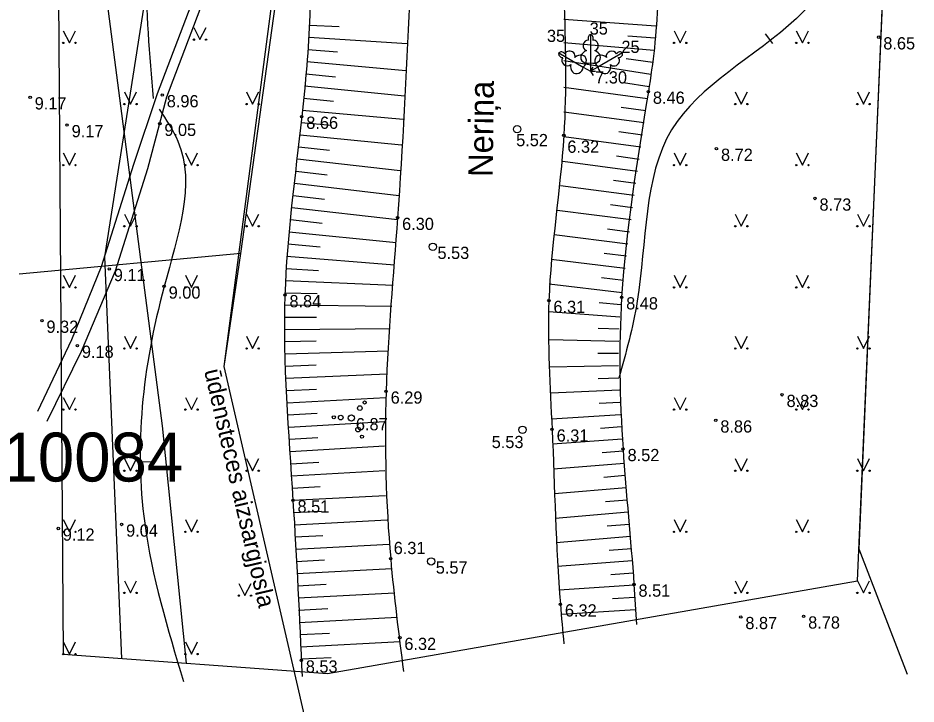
# Model space of a CAD drawing. Extents: x 496127 to 496334, y 303823 to 303967.
# Drawn here: x 496197.9 to 496234.65, y 303857.96 to 303886.02 of the extents above; entities that cross this region are included whole.
import ezdxf

# ---------------------------------------------------------------- set-up
doc = ezdxf.new("R2010")
doc.units = 0
for name, color, linetype in [('APGR_AIZS_####_####_#', 7, 'Continuous'), ('APGR_AIZS_####_TKST_#', 7, 'Continuous'), ('CELI_TAKA_####_####_#', 7, 'Continuous'), ('GAZE_VADP_ASP1_####_#', 7, 'Continuous'), ('HIDG_AATZ_####_TKST_#', 7, 'Continuous'), ('HIDG_ELEM_####_####_#', 7, 'Continuous'), ('HIDG_HNOS_####_TKST_#', 7, 'Continuous'), ('HIDG_PLIN_####_####_#', 7, 'Continuous'), ('Level 24', 7, 'Continuous'), ('Level 59', 7, 'Continuous'), ('RAMI_UZMR_####_####_#', 7, 'Continuous'), ('RELJ_AATZ_####_TKST_#', 7, 'Continuous'), ('RELJ_ELEM_####_####_#', 7, 'Continuous'), ('RELJ_HORZ_PAMT_####_#', 7, 'Continuous'), ('RELJ_NOGA_####_####_#', 7, 'Continuous'), ('SAKT_VADP_KABE_####_#', 7, 'Continuous'), ('TERT_DIAM_####_TKST_#', 7, 'Continuous'), ('TERT_ELEM_####_####_#', 7, 'Continuous')]:
    doc.layers.add(name, color=color, linetype=linetype)

msp = doc.modelspace()

# ---------------------------------------------------------------- linework, layer by layer
at = {"layer": 'APGR_AIZS_####_####_#'}
msp.add_lwpolyline([(496206.5, 303871.056), (496206.335, 303871.77), (496213.935, 303929.615)], dxfattribs=at)
at = {"layer": 'CELI_TAKA_####_####_#'}
for points in [[(496198.714, 303869.933), (496200.104, 303872.87), (496201.314, 303875.855), (496202.637, 303880.037), (496203.613, 303882.939), (496206.254, 303889.883), (496210.709, 303896.123), (496215.063, 303897.39)], [(496199.09, 303869.522), (496200.5, 303872.394), (496201.881, 303875.679), (496203.215, 303879.862), (496203.987, 303882.797), (496206.61, 303889.693), (496210.953, 303895.777), (496213.057, 303896.39)]]:
    msp.add_lwpolyline(points, dxfattribs=at)
at = {"layer": 'GAZE_VADP_ASP1_####_#'}
msp.add_lwpolyline([(496204.788, 303859.627), (496203.806, 303869.341), (496199.437, 303902.962)], dxfattribs=at)
at = {"layer": 'HIDG_ELEM_####_####_#'}
for centre in [(496218.324, 303881.471), (496214.879, 303876.663), (496218.547, 303869.176), (496214.81, 303863.79)]:
    msp.add_circle(centre, 0.15, dxfattribs=at)
at = {"layer": 'HIDG_PLIN_####_####_#'}
for points in [[(496220.243, 303886.863), (496220.236, 303881.217), (496219.625, 303874.455), (496219.756, 303869.191), (496220.095, 303862.036), (496220.238, 303860.42)], [(496213.924, 303886.643), (496213.431, 303877.849), (496212.963, 303870.744), (496213.15, 303863.904), (496213.673, 303859.283)]]:
    msp.add_spline(points, degree=3, dxfattribs=at)
at = {"layer": 'Level 24'}
for points in [[(496207.017, 303876.387), (496214.972, 303933.586)], [(496234.652, 303919.252), (496232.313, 303864.302)], [(496207.017, 303876.387), (496197.941, 303875.547)], [(496206.335, 303871.77), (496207.017, 303876.387)], [(496210.502, 303853.691), (496206.335, 303871.77)], [(496232.313, 303864.302), (496234.289, 303859.174)]]:
    msp.add_lwpolyline(points, dxfattribs=at)
at = {"layer": 'RAMI_UZMR_####_####_#'}
for p, q in [((496232.25, 303863), (496234.504, 303914.713)), ((496199.386, 303909.951), (496199.75, 303860)), ((496210.565, 303859.199), (496232.25, 303863)), ((496199.75, 303860), (496210.565, 303859.199))]:
    msp.add_line(p, q, dxfattribs=at)
at = {"layer": 'RELJ_ELEM_####_####_#'}
for centre in [(496233.126, 303885.236), (496223.696, 303883.01), (496198.395, 303882.78), (496203.8, 303882.868), (496209.51, 303881.987), (496199.907, 303881.643), (496203.702, 303881.695), (496220.236, 303881.217), (496226.484, 303880.676), (496230.515, 303878.639), (496213.431, 303877.849), (496201.634, 303875.756), (496203.878, 303875.039), (496208.821, 303874.686), (496222.602, 303874.598), (496219.625, 303874.455), (496198.876, 303873.641), (496200.326, 303872.617), (496212.963, 303870.744), (496229.167, 303870.606), (496226.456, 303869.561), (496219.756, 303869.191), (496222.659, 303868.391), (496209.151, 303866.287), (496199.545, 303865.137), (496202.136, 303865.302), (496213.15, 303863.904), (496223.107, 303862.846), (496220.095, 303862.036), (496227.48, 303861.519), (496230.051, 303861.541), (496213.524, 303860.667), (496209.49, 303859.74)]:
    msp.add_circle(centre, 0.05, dxfattribs=at)
at = {"layer": 'RELJ_HORZ_PAMT_####_#'}
for p, q in [((496228.476, 303885.377), (496228.782, 303884.981)), ((496203.345, 303867.845), (496202.845, 303867.861))]:
    msp.add_line(p, q, dxfattribs=at)
for points in [[(496203.439, 303882.731), (496203.179, 303888.078), (496203.725, 303896.297), (496203.725, 303904.242), (496206.353, 303911.685), (496206.353, 303912.842)], [(496233.953, 303892.531), (496229.761, 303886.007), (496224.648, 303881.444), (496223.24, 303874.437), (496222.492, 303871.289)], [(496203.672, 303882.286), (496204.44, 303880.984), (496203.878, 303875.039), (496203.082, 303865.35), (496204.666, 303858.881)]]:
    msp.add_spline(points, degree=3, dxfattribs=at)
at = {"layer": 'RELJ_NOGA_####_####_#'}
for p, q in [((496224.008, 303885.694), (496220.242, 303885.961)), ((496209.825, 303885.732), (496211.037, 303885.677)), ((496209.798, 303885.232), (496213.83, 303884.974)), ((496223.973, 303885.195), (496222.853, 303885.274)), ((496223.937, 303884.696), (496220.24, 303885.005)), ((496209.763, 303884.734), (496210.974, 303884.641)), ((496209.721, 303884.235), (496213.769, 303883.875)), ((496223.804, 303883.705), (496220.24, 303884.274)), ((496223.879, 303884.2), (496222.788, 303884.357)), ((496209.675, 303883.737), (496210.894, 303883.62)), ((496209.627, 303883.24), (496213.711, 303882.841)), ((496223.656, 303882.716), (496220.238, 303883.183)), ((496223.725, 303883.212), (496222.679, 303883.372)), ((496209.578, 303882.742), (496210.81, 303882.625)), ((496223.588, 303882.221), (496222.583, 303882.358)), ((496209.532, 303882.244), (496213.657, 303881.881)), ((496223.521, 303881.726), (496220.237, 303882.174)), ((496209.489, 303881.746), (496210.731, 303881.632)), ((496209.442, 303881.248), (496213.598, 303880.83)), ((496223.453, 303881.23), (496222.488, 303881.362)), ((496223.385, 303880.735), (496220.236, 303881.163)), ((496209.39, 303880.751), (496210.643, 303880.616)), ((496209.334, 303880.254), (496213.539, 303879.777)), ((496223.251, 303879.744), (496220.195, 303880.155)), ((496223.318, 303880.239), (496222.39, 303880.365)), ((496209.276, 303879.758), (496210.546, 303879.607)), ((496223.185, 303879.248), (496222.275, 303879.37)), ((496209.218, 303879.261), (496213.482, 303878.755)), ((496223.119, 303878.753), (496220.098, 303879.151)), ((496209.159, 303878.764), (496210.447, 303878.612)), ((496209.101, 303878.268), (496213.427, 303877.775)), ((496223.054, 303878.257), (496222.148, 303878.375)), ((496222.989, 303877.761), (496219.971, 303878.15)), ((496209.045, 303877.771), (496210.351, 303877.629)), ((496208.993, 303877.274), (496213.37, 303876.836)), ((496222.863, 303876.769), (496219.836, 303877.151)), ((496222.925, 303877.265), (496222.019, 303877.381)), ((496208.945, 303876.776), (496210.264, 303876.657)), ((496208.903, 303876.278), (496213.311, 303875.927)), ((496222.741, 303875.777), (496219.718, 303876.14)), ((496222.801, 303876.273), (496221.893, 303876.386)), ((496208.868, 303875.779), (496210.192, 303875.695)), ((496222.681, 303875.28), (496221.779, 303875.387)), ((496208.841, 303875.28), (496213.253, 303875.092)), ((496222.623, 303874.784), (496219.641, 303875.128)), ((496208.823, 303874.78), (496210.143, 303874.747)), ((496208.815, 303874.28), (496213.192, 303874.229)), ((496222.569, 303874.286), (496221.686, 303874.37)), ((496222.528, 303873.788), (496219.627, 303874)), ((496208.812, 303873.78), (496210.117, 303873.78)), ((496208.815, 303873.28), (496213.129, 303873.322)), ((496222.5, 303873.289), (496221.64, 303873.324)), ((496208.823, 303872.78), (496210.105, 303872.808)), ((496222.484, 303872.789), (496219.641, 303872.852)), ((496208.835, 303872.28), (496213.066, 303872.402)), ((496222.477, 303872.289), (496221.63, 303872.29)), ((496208.852, 303871.781), (496210.107, 303871.827)), ((496222.481, 303871.789), (496219.666, 303871.743)), ((496208.872, 303871.281), (496213.006, 303871.464)), ((496222.492, 303871.289), (496221.649, 303871.265)), ((496208.895, 303870.782), (496210.119, 303870.84)), ((496222.51, 303870.79), (496219.7, 303870.671)), ((496208.92, 303870.282), (496212.95, 303870.495)), ((496222.534, 303870.29), (496221.689, 303870.244)), ((496208.947, 303869.783), (496210.142, 303869.849)), ((496222.563, 303869.791), (496219.739, 303869.616)), ((496208.976, 303869.284), (496212.912, 303869.512)), ((496222.595, 303869.292), (496221.744, 303869.234)), ((496209.006, 303868.785), (496210.175, 303868.855)), ((496222.63, 303868.793), (496219.779, 303868.592)), ((496209.036, 303868.286), (496212.898, 303868.518)), ((496222.666, 303868.295), (496221.806, 303868.23)), ((496209.066, 303867.787), (496210.216, 303867.856)), ((496222.704, 303867.796), (496219.815, 303867.57)), ((496209.096, 303867.287), (496212.908, 303867.506)), ((496222.745, 303867.298), (496221.871, 303867.225)), ((496209.124, 303866.788), (496210.263, 303866.851)), ((496209.151, 303866.289), (496212.943, 303866.49)), ((496222.787, 303866.8), (496219.85, 303866.549)), ((496222.83, 303866.302), (496221.941, 303866.224)), ((496209.177, 303865.79), (496210.315, 303865.849)), ((496222.873, 303865.803), (496219.886, 303865.543)), ((496209.203, 303865.29), (496213.003, 303865.487)), ((496222.916, 303865.305), (496222.013, 303865.227)), ((496209.228, 303864.791), (496210.373, 303864.85)), ((496222.959, 303864.807), (496219.929, 303864.552)), ((496209.254, 303864.292), (496213.088, 303864.49)), ((496223, 303864.309), (496222.086, 303864.234)), ((496209.28, 303863.792), (496210.438, 303863.852)), ((496223.039, 303863.81), (496219.981, 303863.58)), ((496209.306, 303863.293), (496213.196, 303863.494)), ((496223.076, 303863.312), (496222.157, 303863.247)), ((496209.332, 303862.794), (496210.508, 303862.855)), ((496223.109, 303862.813), (496220.047, 303862.618)), ((496209.358, 303862.294), (496213.309, 303862.499)), ((496223.141, 303862.314), (496222.225, 303862.255)), ((496209.384, 303861.795), (496210.578, 303861.857)), ((496223.173, 303861.815), (496220.132, 303861.621)), ((496209.409, 303861.296), (496213.422, 303861.503)), ((496209.435, 303860.796), (496210.648, 303860.859)), ((496209.461, 303860.297), (496213.535, 303860.508)), ((496209.487, 303859.798), (496210.718, 303859.861))]:
    msp.add_line(p, q, dxfattribs=at)
for points in [[(496209.866, 303887.231), (496209.839, 303886.14), (496209.51, 303881.987), (496208.821, 303874.686), (496209.151, 303866.287), (496209.524, 303859.08)], [(496224.079, 303886.691), (496223.944, 303884.79), (496223.696, 303883.01), (496222.602, 303874.598), (496222.659, 303868.391), (496223.107, 303862.846), (496223.211, 303861.207)]]:
    msp.add_spline(points, degree=3, dxfattribs=at)
at = {"layer": 'SAKT_VADP_KABE_####_#'}
msp.add_lwpolyline([(496210.224, 303932.504), (496206.983, 303911.574), (496201.442, 303876.244), (496202.133, 303859.823)], dxfattribs=at)
at = {"layer": 'TERT_ELEM_####_####_#'}
for p, q in [((496205.096, 303885.635), (496205.346, 303885.135)), ((496205.346, 303885.135), (496205.596, 303885.635)), ((496199.75, 303885.5), (496200, 303885)), ((496200, 303885), (496200.25, 303885.5)), ((496224.75, 303885.5), (496225, 303885)), ((496225, 303885), (496225.25, 303885.5)), ((496229.75, 303885.5), (496230, 303885)), ((496230, 303885), (496230.25, 303885.5)), ((496221.334, 303884.189), (496221.334, 303883.842)), ((496221.033, 303884.015), (496221.334, 303883.842)), ((496221.334, 303883.842), (496221.434, 303884.015)), ((496221.635, 303884.015), (496221.334, 303883.842)), ((496221.334, 303883.842), (496221.534, 303883.842)), ((496221.334, 303883.842), (496221.434, 303883.669)), ((496202.25, 303883), (496202.5, 303882.5)), ((496202.5, 303882.5), (496202.75, 303883)), ((496207.25, 303883), (496207.5, 303882.5)), ((496207.5, 303882.5), (496207.75, 303883)), ((496227.25, 303883), (496227.5, 303882.5)), ((496227.5, 303882.5), (496227.75, 303883)), ((496232.25, 303883), (496232.5, 303882.5)), ((496232.5, 303882.5), (496232.75, 303883)), ((496199.75, 303880.5), (496200, 303880)), ((496200, 303880), (496200.25, 303880.5)), ((496204.75, 303880.5), (496205, 303880)), ((496205, 303880), (496205.25, 303880.5)), ((496224.75, 303880.5), (496225, 303880)), ((496225, 303880), (496225.25, 303880.5)), ((496229.75, 303880.5), (496230, 303880)), ((496230, 303880), (496230.25, 303880.5)), ((496202.25, 303878), (496202.5, 303877.5)), ((496202.5, 303877.5), (496202.75, 303878)), ((496207.25, 303878), (496207.5, 303877.5)), ((496207.5, 303877.5), (496207.75, 303878)), ((496227.25, 303878), (496227.5, 303877.5)), ((496227.5, 303877.5), (496227.75, 303878)), ((496232.25, 303878), (496232.5, 303877.5)), ((496232.5, 303877.5), (496232.75, 303878)), ((496199.75, 303875.5), (496200, 303875)), ((496200, 303875), (496200.25, 303875.5)), ((496204.75, 303875.5), (496205, 303875)), ((496205, 303875), (496205.25, 303875.5)), ((496224.75, 303875.5), (496225, 303875)), ((496225, 303875), (496225.25, 303875.5)), ((496229.75, 303875.5), (496230, 303875)), ((496230, 303875), (496230.25, 303875.5)), ((496202.25, 303873), (496202.5, 303872.5)), ((496202.5, 303872.5), (496202.75, 303873)), ((496207.25, 303873), (496207.5, 303872.5)), ((496207.5, 303872.5), (496207.75, 303873)), ((496227.25, 303873), (496227.5, 303872.5)), ((496227.5, 303872.5), (496227.75, 303873)), ((496232.25, 303873), (496232.5, 303872.5)), ((496232.5, 303872.5), (496232.75, 303873)), ((496199.75, 303870.5), (496200, 303870)), ((496200, 303870), (496200.25, 303870.5)), ((496204.75, 303870.5), (496205, 303870)), ((496205, 303870), (496205.25, 303870.5)), ((496224.75, 303870.5), (496225, 303870)), ((496225, 303870), (496225.25, 303870.5)), ((496229.75, 303870.5), (496230, 303870)), ((496230, 303870), (496230.25, 303870.5)), ((496202.25, 303868), (496202.5, 303867.5)), ((496202.5, 303867.5), (496202.75, 303868)), ((496207.25, 303868), (496207.5, 303867.5)), ((496207.5, 303867.5), (496207.75, 303868)), ((496227.25, 303868), (496227.5, 303867.5)), ((496227.5, 303867.5), (496227.75, 303868)), ((496232.25, 303868), (496232.5, 303867.5)), ((496232.5, 303867.5), (496232.75, 303868)), ((496199.75, 303865.5), (496200, 303865)), ((496200, 303865), (496200.25, 303865.5)), ((496204.75, 303865.5), (496205, 303865)), ((496205, 303865), (496205.25, 303865.5)), ((496224.75, 303865.5), (496225, 303865)), ((496225, 303865), (496225.25, 303865.5)), ((496229.75, 303865.5), (496230, 303865)), ((496230, 303865), (496230.25, 303865.5)), ((496202.25, 303863), (496202.5, 303862.5)), ((496202.5, 303862.5), (496202.75, 303863)), ((496206.937, 303862.89), (496207.187, 303862.39)), ((496207.187, 303862.39), (496207.437, 303862.89)), ((496227.25, 303863), (496227.5, 303862.5)), ((496227.5, 303862.5), (496227.75, 303863)), ((496232.25, 303863), (496232.5, 303862.5)), ((496232.5, 303862.5), (496232.75, 303863)), ((496199.75, 303860.5), (496200, 303860)), ((496200, 303860), (496200.25, 303860.5)), ((496204.75, 303860.5), (496205, 303860)), ((496205, 303860), (496205.25, 303860.5))]:
    msp.add_line(p, q, dxfattribs=at)
for points in [[(496221.334, 303885.342), (496221.334, 303884.189)], [(496221.424, 303885.11), (496221.423, 303885.111)], [(496220.035, 303884.592), (496221.033, 303884.015)], [(496220.281, 303884.553), (496220.28, 303884.553)], [(496222.633, 303884.592), (496221.635, 303884.015)], [(496222.477, 303884.398), (496222.477, 303884.4)]]:
    msp.add_lwpolyline(points, dxfattribs=at)
for centre, radius in [((496199.75, 303885), 0.028), ((496200.25, 303885), 0.0263), ((496205.096, 303885.135), 0.028), ((496205.596, 303885.135), 0.0263), ((496224.75, 303885), 0.028), ((496225.25, 303885), 0.0263), ((496229.75, 303885), 0.028), ((496230.25, 303885), 0.0263), ((496202.25, 303882.5), 0.028), ((496202.75, 303882.5), 0.0263), ((496207.25, 303882.5), 0.028), ((496207.75, 303882.5), 0.0263), ((496227.25, 303882.5), 0.028), ((496227.75, 303882.5), 0.0263), ((496232.25, 303882.5), 0.028), ((496232.75, 303882.5), 0.0263), ((496199.75, 303880), 0.028), ((496200.25, 303880), 0.0263), ((496204.75, 303880), 0.028), ((496205.25, 303880), 0.0263), ((496224.75, 303880), 0.028), ((496225.25, 303880), 0.0263), ((496229.75, 303880), 0.028), ((496230.25, 303880), 0.0263), ((496202.25, 303877.5), 0.028), ((496202.75, 303877.5), 0.0263), ((496207.25, 303877.5), 0.028), ((496207.75, 303877.5), 0.0263), ((496227.25, 303877.5), 0.028), ((496227.75, 303877.5), 0.0263), ((496232.25, 303877.5), 0.028), ((496232.75, 303877.5), 0.0263), ((496199.75, 303875), 0.028), ((496200.25, 303875), 0.0263), ((496204.75, 303875), 0.028), ((496205.25, 303875), 0.0263), ((496224.75, 303875), 0.028), ((496225.25, 303875), 0.0263), ((496229.75, 303875), 0.028), ((496230.25, 303875), 0.0263), ((496202.25, 303872.5), 0.028), ((496202.75, 303872.5), 0.0263), ((496207.25, 303872.5), 0.028), ((496207.75, 303872.5), 0.0263), ((496227.25, 303872.5), 0.028), ((496227.75, 303872.5), 0.0263), ((496232.25, 303872.5), 0.028), ((496232.75, 303872.5), 0.0263), ((496211.888, 303870.061), 0.096), ((496212.084, 303870.292), 0.064), ((496199.75, 303870), 0.028), ((496200.25, 303870), 0.0263), ((496204.75, 303870), 0.028), ((496205.25, 303870), 0.0263), ((496224.75, 303870), 0.028), ((496225.25, 303870), 0.0263), ((496229.75, 303870), 0.028), ((496230.25, 303870), 0.0263), ((496210.822, 303869.687), 0.064), ((496211.106, 303869.674), 0.096), ((496211.54, 303869.653), 0.128), ((496211.816, 303869.186), 0.096), ((496211.974, 303868.897), 0.064), ((496202.25, 303867.5), 0.028), ((496202.75, 303867.5), 0.0263), ((496207.25, 303867.5), 0.028), ((496207.75, 303867.5), 0.0263), ((496227.25, 303867.5), 0.028), ((496227.75, 303867.5), 0.0263), ((496232.25, 303867.5), 0.028), ((496232.75, 303867.5), 0.0263), ((496199.75, 303865), 0.028), ((496200.25, 303865), 0.0263), ((496204.75, 303865), 0.028), ((496205.25, 303865), 0.0263), ((496224.75, 303865), 0.028), ((496225.25, 303865), 0.0263), ((496229.75, 303865), 0.028), ((496230.25, 303865), 0.0263), ((496202.25, 303862.5), 0.028), ((496202.75, 303862.5), 0.0263), ((496227.25, 303862.5), 0.028), ((496227.75, 303862.5), 0.0263), ((496232.25, 303862.5), 0.028), ((496232.75, 303862.5), 0.0263), ((496206.936, 303862.389), 0.028), ((496207.436, 303862.389), 0.0263), ((496199.75, 303860), 0.028), ((496200.25, 303860), 0.0263), ((496204.75, 303860), 0.028), ((496205.25, 303860), 0.0263)]:
    msp.add_circle(centre, radius, dxfattribs=at)
for centre, major_axis, ratio, start_param, end_param in [((496221.334, 303885.192), (0, -0.15), 0.707107, 3.14537, 5.287485), ((496221.334, 303885.192), (0, -0.15), 0.707107, 0.995701, 3.137816), ((496221.206, 303884.897), (-0.039, -0.212), 0.861323, 3.141593, 6.283185), ((496221.462, 303884.897), (0.039, -0.212), 0.861323, 0, 3.141593), ((496220.165, 303884.517), (0.13, -0.075), 0.707107, 3.14537, 5.287485), ((496220.165, 303884.517), (0.13, -0.075), 0.707107, 0.995701, 3.137816), ((496220.484, 303884.481), (0.203, -0.073), 0.861323, 0, 3.141593), ((496220.865, 303884.216), (-0.236, -0.218), 0.814445, 1.531171, 4.712389), ((496221.244, 303884.435), (0.307, 0.095), 0.814445, 1.570796, 4.752015), ((496221.424, 303884.435), (-0.307, 0.095), 0.814445, 1.531171, 4.712389), ((496221.803, 303884.216), (0.236, -0.218), 0.814445, 1.570796, 4.752015), ((496222.184, 303884.481), (-0.203, -0.073), 0.861323, 3.141593, 6.283185), ((496222.503, 303884.517), (-0.13, -0.075), 0.707107, 3.14537, 5.287485), ((496222.503, 303884.517), (-0.13, -0.075), 0.707107, 0.995701, 3.137816), ((496220.356, 303884.258), (0.165, -0.14), 0.861323, 3.141593, 6.283185), ((496220.776, 303884.061), (0.071, 0.313), 0.814445, 1.570796, 4.752015), ((496221.892, 303884.061), (-0.071, 0.313), 0.814445, 1.531171, 4.712389), ((496222.312, 303884.258), (-0.165, -0.14), 0.861323, 0, 3.141593)]:
    msp.add_ellipse(centre, major_axis=major_axis, ratio=ratio, start_param=start_param, end_param=end_param, dxfattribs=at)

# ---------------------------------------------------------------- texts
at = {"layer": 'APGR_AIZS_####_TKST_#'}
msp.add_text('ūdensteces aizsargjosla', height=0.7, rotation=282.9788, dxfattribs=at).set_placement((496205.512, 303871.584))
at = {"layer": 'HIDG_AATZ_####_TKST_#'}
for s, p in [(' 5.52', (496218.1, 303880.777)), (' 5.53', (496214.879, 303876.163)), (' 5.53', (496217.099, 303868.426)), (' 5.57', (496214.81, 303863.29))]:
    msp.add_text(s, height=0.5, dxfattribs=at).set_placement(p)
at = {"layer": 'HIDG_HNOS_####_TKST_#'}
msp.add_text('Neriņa', height=1, rotation=89.2349, dxfattribs=at).set_placement((496217.325, 303879.511))
at = {"layer": 'Level 59'}
msp.add_text('80760110084', height=2, dxfattribs=at).set_placement((496188.298, 303867.059))
at = {"layer": 'RELJ_AATZ_####_TKST_#'}
for s, p in [(' 8.65', (496233.126, 303884.736)), (' 7.30', (496221.334, 303883.342)), (' 8.46', (496223.696, 303882.51)), (' 9.17', (496198.395, 303882.28)), (' 8.96', (496203.8, 303882.368)), (' 8.66', (496209.51, 303881.487)), (' 9.17', (496199.907, 303881.143)), (' 9.05', (496203.702, 303881.195)), (' 6.32', (496220.194, 303880.508)), (' 8.72', (496226.484, 303880.176)), (' 8.73', (496230.515, 303878.139)), (' 6.30', (496213.431, 303877.349)), (' 9.11', (496201.634, 303875.256)), (' 9.00', (496203.878, 303874.539)), (' 8.84', (496208.821, 303874.186)), (' 8.48', (496222.602, 303874.098)), (' 6.31', (496219.625, 303873.955)), (' 9.32', (496198.876, 303873.141)), (' 9.18', (496200.326, 303872.117)), (' 6.29', (496212.963, 303870.244)), (' 8.83', (496229.167, 303870.106)), (' 6.87', (496211.54, 303869.153)), (' 8.86', (496226.456, 303869.061)), (' 6.31', (496219.756, 303868.691)), (' 8.52', (496222.659, 303867.891)), (' 8.51', (496209.151, 303865.787)), (' 9.12', (496199.545, 303864.637)), (' 9.04', (496202.136, 303864.802)), (' 6.31', (496213.088, 303864.09)), (' 8.51', (496223.107, 303862.346)), (' 6.32', (496220.095, 303861.536)), (' 8.87', (496227.48, 303861.019)), (' 8.78', (496230.051, 303861.041)), (' 6.32', (496213.524, 303860.167)), (' 8.53', (496209.49, 303859.24))]:
    msp.add_text(s, height=0.5, dxfattribs=at).set_placement(p)
at = {"layer": 'TERT_DIAM_####_TKST_#'}
for s, p in [(' 35', (496221.109, 303885.342)), (' 35', (496219.36, 303885.042)), (' 25', (496222.408, 303884.592))]:
    msp.add_text(s, height=0.5, dxfattribs=at).set_placement(p)

doc.saveas('drawing.dxf')
